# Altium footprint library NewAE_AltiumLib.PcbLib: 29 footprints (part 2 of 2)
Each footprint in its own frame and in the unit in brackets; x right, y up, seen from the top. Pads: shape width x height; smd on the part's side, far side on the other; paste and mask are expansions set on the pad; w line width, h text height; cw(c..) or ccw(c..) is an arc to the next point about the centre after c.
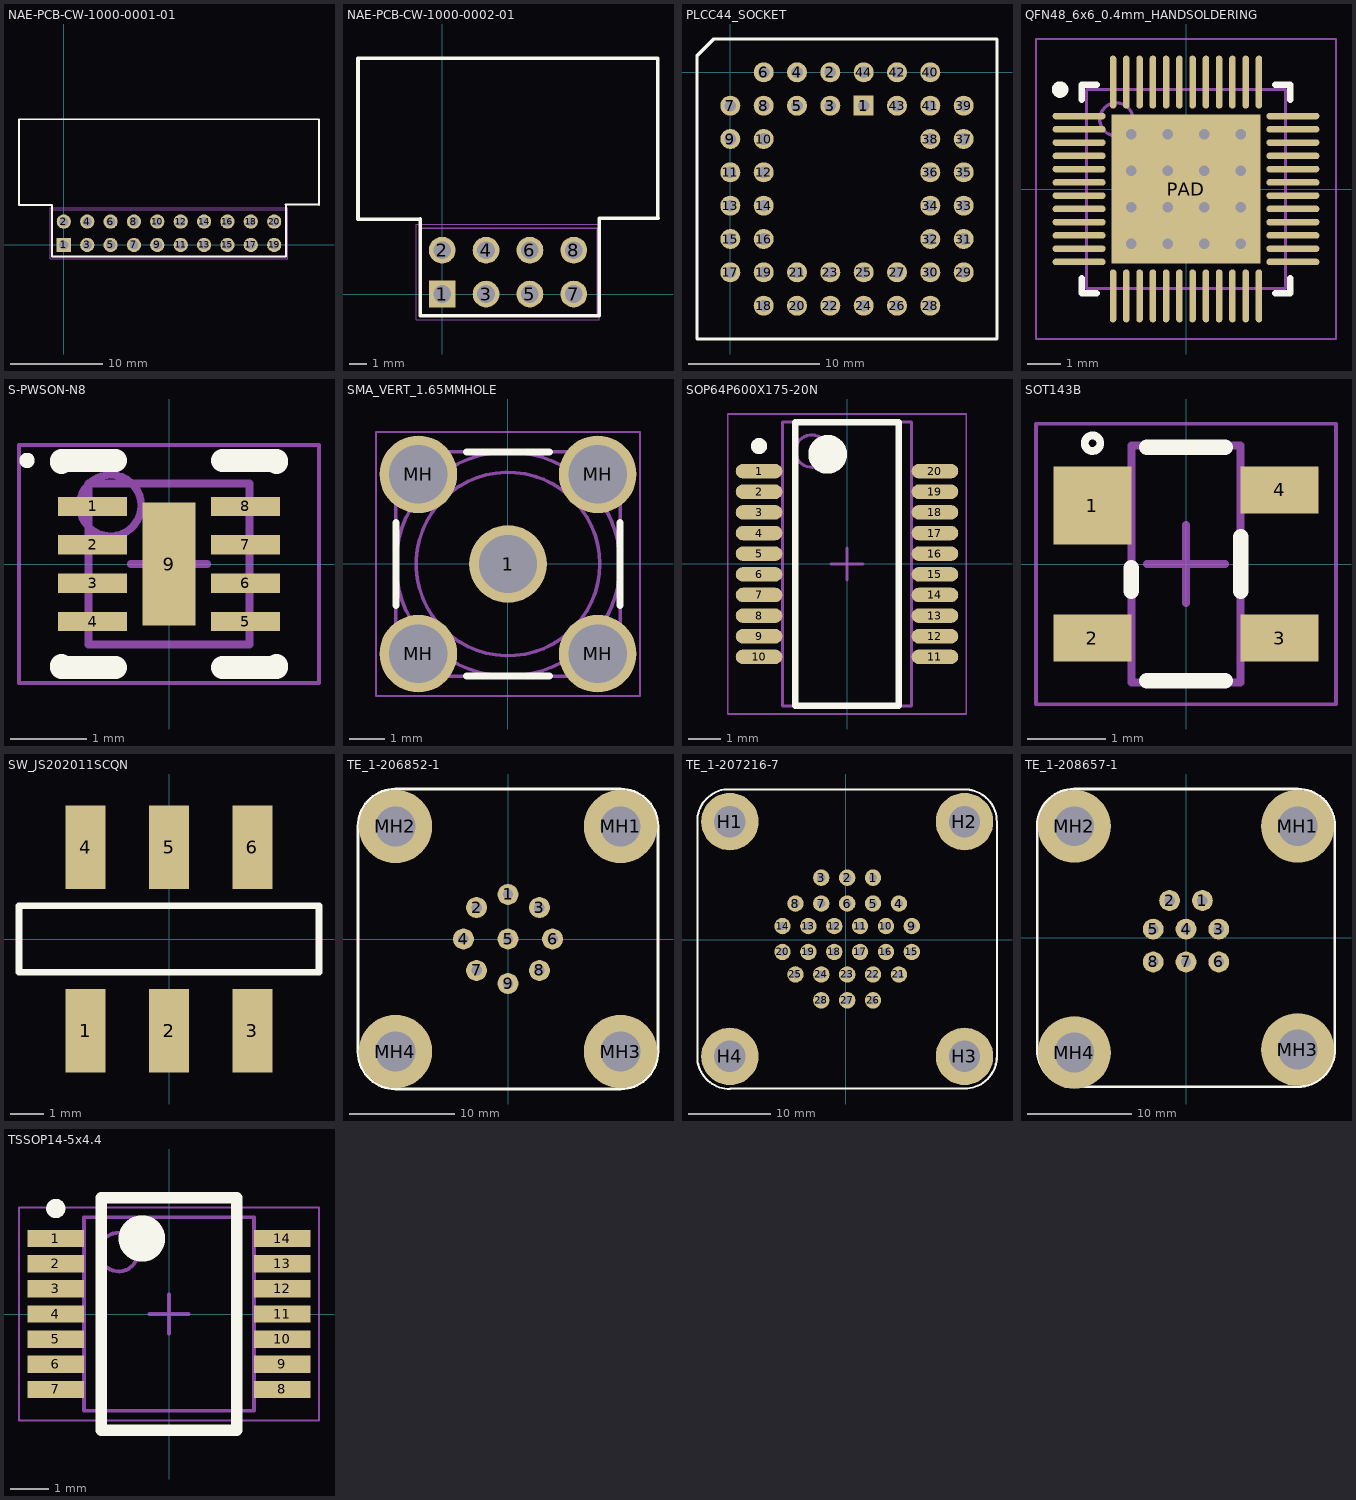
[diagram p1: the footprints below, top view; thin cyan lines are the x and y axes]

## NAE-PCB-CW-1000-0001-01 [mm] "High Temp Terminal Body, 2x10 Pins, R/A, 2.54mm Pitch, Male"
height 9.2
pads (20):
  rect 1.55x1.55 hole 1.02: 1(0,0)
  round 1.55 hole 1.02: 2(0,2.54) 3(2.54,0) 4(2.54,2.54) 5(5.08,0) 6(5.08,2.54) 7(7.62,0) 8(7.62,2.54) 9(10.16,0) 10(10.16,2.54) 11(12.7,0) 12(12.7,2.54) 13(15.24,0) 14(15.24,2.54) 15(17.78,0) 16(17.78,2.54) 17(20.32,0) 18(20.32,2.54) 19(22.86,0) 20(22.86,2.54)
Top Overlay:
  lines w0.2: -1.27,3.81 -1.27,-1.27 24.13,-1.27 24.13,3.81
  lines w0.203: -1.27,3.81 -1.27,4.37 -1.3,4.34 -4.875,4.34 -4.875,13.66 -4.875,13.66 27.735,13.66 ; 24.13,3.81 24.13,4.37 24.1,4.4 27.675,4.4 27.735,4.34 27.735,13.66 ; 27.735,13.66 27.735,13.66
Top 3D:
  lines w0.1: -1.27,-1.27 24.13,-1.27 24.13,3.81 -1.27,3.81 -1.27,-1.27
Top Courtyard:
  lines w0.05: -1.495,-1.495 24.355,-1.495 24.355,4.035 -1.495,4.035 -1.495,-1.495
3D body "75867_y04_asm.stp": height 9.27, standoff -3.07, extent -4.875,-0.31 27.735,13.66

## NAE-PCB-CW-1000-0002-01 [mm] "High Temp Terminal Body, 2x4 Pins, R/A, 2.54mm Pitch, Male"
height 9.2
pads (8):
  rect 1.55x1.55 hole 1.02: 1(0,0)
  round 1.55 hole 1.02: 2(0,2.54) 3(2.54,0) 4(2.54,2.54) 5(5.08,0) 7(7.62,0) 8(7.62,2.54)
  round 1.55 hole 1.02 mask+0.102: 6(5.08,2.54)
Top Overlay:
  lines w0.2: -1.27,3.81 -1.27,-1.27 9.1,-1.27
  lines w0.203: -1.27,3.81 -1.27,4.37 -1.3,4.34 -4.875,4.34 -4.875,13.66 -4.875,13.66 12.495,13.66 12.495,4.405 ; 9.1,-1.27 9.1,4.4 ; 9.13,4.37 9.1,4.4 ; 12.5,4.4 9.1,4.4
Top 3D:
  lines w0.1: -1.27,-1.27 9,-1.27 9,3.81 -1.27,3.81 -1.27,-1.27
Top Courtyard:
  lines w0.05: -1.495,-1.495 9.1,-1.495 9.1,-0.113 9.1,2.653 9.1,4.035 -1.495,4.035 -1.495,-1.495
3D body "75867132lf.stp": height 9.27, standoff -3.07, extent -4.875,-0.31 12.495,13.66

## PLCC44_SOCKET [mil]
pads (44):
  rect 60x60 hole 35: 1(400,-100)
  round 60 hole 35: 2(300,0) 3(300,-100) 4(200,0) 5(200,-100) 6(100,0) 7(0,-100) 8(100,-100) 9(0,-200) 10(100,-200) 11(0,-300) 12(100,-300) 13(0,-400) 14(100,-400) 15(0,-500) 16(100,-500) 17(0,-600) 18(100,-700) 19(100,-600) 20(200,-700) 21(200,-600) 22(300,-700) 23(300,-600) 24(400,-700) 25(400,-600) 26(500,-700) 27(500,-600) 28(600,-700) 29(700,-600) 30(600,-600) 31(700,-500) 32(600,-500) 33(700,-400) 34(600,-400) 35(700,-300) 36(600,-300) 37(700,-200) 38(600,-200) 39(700,-100) 40(600,0) 41(600,-100) 42(500,0) 43(500,-100) 44(400,0)
Top Overlay:
  lines w10: -100,-800 -100,50 -50,100 800,100 800,-800 -100,-800
3D body "10376.stp": height 301.57, standoff -129.92, extent -91.92,-791.92 791.94,91.94

## QFN48_6x6_0.4mm_HANDSOLDERING [mm] "QFN48, 6x6 body, hand soldering (long leads)"
height 0.8
pads (49):
  oval 1.6x0.2 smd: 1(-3.225,2.2) 2(-3.225,1.8) 3(-3.225,1.4) 4(-3.225,1) 5(-3.225,0.6) 6(-3.225,0.2) 7(-3.225,-0.2) 8(-3.225,-0.6) 9(-3.225,-1) 10(-3.225,-1.4) 11(-3.225,-1.8) 12(-3.225,-2.2) 25(3.225,-2.2) 26(3.225,-1.8) 27(3.225,-1.4) 28(3.225,-1) 29(3.225,-0.6) 30(3.225,-0.2) 31(3.225,0.2) 32(3.225,0.6) 33(3.225,1) 34(3.225,1.4) 35(3.225,1.8) 36(3.225,2.2)
  oval 0.2x1.6 smd: 13(-2.2,-3.225) 14(-1.8,-3.225) 15(-1.4,-3.225) 16(-1,-3.225) 17(-0.6,-3.225) 18(-0.2,-3.225) 19(0.2,-3.225) 20(0.6,-3.225) 21(1,-3.225) 22(1.4,-3.225) 23(1.8,-3.225) 24(2.2,-3.225) 37(2.2,3.225) 38(1.8,3.225) 39(1.4,3.225) 40(1,3.225) 41(0.6,3.225) 42(0.2,3.225) 43(-0.2,3.225) 44(-0.6,3.225) 45(-1,3.225) 46(-1.4,3.225) 47(-1.8,3.225) 48(-2.2,3.225)
  rect 4.5x4.5 smd: PAD(0,0)
via -1.65,1.65 diameter 0.6 hole 0.32
via -0.55,1.65 diameter 0.6 hole 0.32
via 0.55,1.65 diameter 0.6 hole 0.32
via 1.65,1.65 diameter 0.6 hole 0.32
via -1.65,0.55 diameter 0.6 hole 0.32
via -0.55,0.55 diameter 0.6 hole 0.32
via 0.55,0.55 diameter 0.6 hole 0.32
via 1.65,0.55 diameter 0.6 hole 0.32
via -1.65,-0.55 diameter 0.6 hole 0.32
via -0.55,-0.55 diameter 0.6 hole 0.32
via 0.55,-0.55 diameter 0.6 hole 0.32
via 1.65,-0.55 diameter 0.6 hole 0.32
via -1.65,-1.65 diameter 0.6 hole 0.32
via -0.55,-1.65 diameter 0.6 hole 0.32
via 0.55,-1.65 diameter 0.6 hole 0.32
via 1.65,-1.65 diameter 0.6 hole 0.32
Top Overlay:
  circle w0.25: c-3.8,3 r0.125
  lines w0.2: -3.15,-2.7 -3.15,-3.15 -2.7,-3.15 ; -3.15,2.7 -3.15,3.15 -2.7,3.15 ; 2.7,-3.15 3.15,-3.15 3.15,-2.7 ; 2.7,3.15 3.15,3.15 3.15,2.7
Top 3D:
  circle w0.1: c-2.1,2.1 r0.5
  lines w0.1: -3,-3 -3,3 3,3 3,-3 -3,-3
Top Courtyard:
  lines w0.05: -4.525,-4.525 -4.525,4.525 4.525,4.525 4.525,-4.525 -4.525,-4.525
  lines w0.1: -0.5,0 0.5,0 ; 0,-0.5 0,0.5
3D body "QFN48_6x6_0.4mm_HANDSOLDERING.step": height 0.8, standoff 0, extent -3.01,-3.01 3.01,3.01

## S-PWSON-N8 [mm] "SON, 8-Leads, Body 2.00x2.00mm, Pitch 0.50mm, Thermal Pad 1.60x0.69mm, IPC Low Density"
height 0.8
pads (9):
  rect 0.9x0.25 smd: 1(-0.995,0.75) 2(-0.995,0.25) 3(-0.995,-0.25) 4(-0.995,-0.75) 5(0.995,-0.75) 6(0.995,-0.25) 7(0.995,0.25) 8(0.995,0.75)
  rect 0.69x1.6 smd: 9(0,0)
Top Overlay:
  circle w0.1: c-1.85,1.35 r0.05
  lines w0.3: -1.4,-1.325 -1.4,-1.35 -0.695,-1.35 ; -1.4,1.325 -1.4,1.35 -0.695,1.35 ; 0.695,-1.35 1.4,-1.35 1.4,-1.325 ; 0.695,1.35 1.4,1.35 1.4,1.325
Top 3D:
  circle w0.1: c-0.762,0.762 r0.4
  lines w0.1: -1.05,-1.05 -1.05,1.05 1.05,1.05 1.05,-1.05 -1.05,-1.05
Top Courtyard:
  lines w0.05: -1.955,-1.55 -1.955,1.55 1.955,1.55 1.955,-1.55 -1.955,-1.55
  lines w0.1: -0.5,0 0.5,0 ; 0,-0.5 0,0.5
3D body "S-PWSON-N8.step": height 0.8, standoff 0, extent -1.1,-1.05 1.1,1.05

## SMA_VERT_1.65MMHOLE [mm] "SMA Straight Jack, 6.35x6.35x9.5mm, Rosenberger Recommended"
height 9.5
pads (5):
  round 2.2 hole 1.65: 1(0,0) MH(-2.54,-2.54) MH(-2.54,2.54) MH(2.54,-2.54) MH(2.54,2.54)
Top Overlay:
  lines w0.2: -3.175,-1.181 -3.175,1.181 ; -1.181,-3.175 1.181,-3.175 ; -1.181,3.175 1.181,3.175 ; 3.175,-1.181 3.175,1.181
Top 3D:
  circle w0.1: c0,0 r0.635
  circle w0.1: c0,0 r2.6
  circle w0.1: c0,0 r3.175
  lines w0.1: -3.19,-2.808 ccw(c0,0) -2.808,-3.191 ; -3.19,2.808 cw(c0,0) -2.808,3.19 ; -3.175,-2.794 -3.175,2.794 ; -3.04,-2.97 -3.04,-2.04 -2.04,-2.04 -2.04,-3.04 -2.97,-3.04 ; -3.04,2.97 -3.04,2.04 -2.04,2.04 -2.04,3.04 -2.97,3.04 ; -2.794,-3.175 2.794,-3.175 ; -2.794,3.175 2.794,3.175 ; -0.1,-0.627 -0.1,0.627 ; 0.1,-0.627 0.1,0.627 ; 2.808,-3.191 ccw(c0,0) 3.191,-2.808 ; 2.808,3.19 cw(c0,0) 3.191,2.808 ; 2.97,3.04 2.04,3.04 2.04,2.04 3.04,2.04 3.04,2.97 ; 2.97,-3.04 2.04,-3.04 2.04,-2.04 3.04,-2.04 3.04,-2.97 ; 3.175,-2.794 3.175,2.794
Top Courtyard:
  lines w0.05: -3.74,-3.74 3.74,-3.74 3.74,3.74 -3.74,3.74 -3.74,-3.74
  lines w0.1: -0.635,0 0.508,0 ; 0,-0.508 0,0.635
3D body "32k101-400l5.stp": height 9.5, standoff -4, extent -3.175,-3.175 3.175,3.175

## SOP64P600X175-20N [mm] "SOP, 20-Leads, Body 8.66x3.91mm, Pitch 0.64mm, IPC Medium Density"
height 1.75
pads (20):
  oval 1.45x0.45 smd: 1(-2.725,2.88) 2(-2.725,2.24) 3(-2.725,1.6) 4(-2.725,0.96) 5(-2.725,0.32) 6(-2.725,-0.32) 7(-2.725,-0.96) 8(-2.725,-1.6) 9(-2.725,-2.24) 10(-2.725,-2.88) 11(2.725,-2.88) 12(2.725,-2.24) 13(2.725,-1.6) 14(2.725,-0.96) 15(2.725,-0.32) 16(2.725,0.32) 17(2.725,0.96) 18(2.725,1.6) 19(2.725,2.24) 20(2.725,2.88)
Top Overlay:
  circle w0.6: c-0.6,3.4 r0.3
  circle w0.25: c-2.725,3.655 r0.125
  lines w0.2: -1.6,-4.4 1.6,-4.4 1.6,4.4 -1.6,4.4 -1.6,-4.4
Top 3D:
  circle w0.1: c-1.1,3.5 r0.5
  lines w0.1: -2,-4.4 2,-4.4 2,4.4 -2,4.4 -2,-4.4
Top Courtyard:
  lines w0.05: -3.7,-4.65 3.7,-4.65 3.7,4.65 -3.7,4.65 -3.7,-4.65
  lines w0.1: -0.5,0 0.5,0 ; 0,-0.5 0,0.5
3D body "SOP64P600X175-20N.step": height 1.75, standoff 0, extent -2.997,-4.4 2.997,4.4

## SOT143B [mm] "SOT143, 4-Leads, Body 2.92x2.37mm, Pitch 1.90mm, IPC Medium Density"
height 1.2
pads (4):
  rect 1x1 smd: 1(-1.2,0.75)
  rect 1x0.6 smd: 2(-1.2,-0.95) 3(1.2,-0.95) 4(1.2,0.95)
Top Overlay:
  circle w0.1: c-1.2,1.55 r0.1
  lines w0.2: -0.7,-0.35 -0.7,-0.05 ; -0.5,-1.5 0.5,-1.5 ; -0.5,1.5 0.5,1.5 ; 0.7,-0.35 0.7,0.35
Top 3D:
  lines w0.1: -0.7,-1.52 -0.7,1.52 0.7,1.52 0.7,-1.52 -0.7,-1.52
Top Courtyard:
  lines w0.05: -1.925,-1.8 -1.925,1.8 1.925,1.8 1.925,-1.8 -1.925,-1.8
  lines w0.1: -0.5,0 0.5,0 ; 0,-0.5 0,0.5
3D body "SOT143B.step": height 1.2, standoff 0.01, extent -1.179,-1.52 1.179,1.52

## SW_JS202011SCQN [mm]
pads (6):
  rect 1.2x2.5 smd paste-25.4 mask-25.4: 1(-2.5,-2.75) 2(0,-2.75) 3(2.5,-2.75) 4(-2.5,2.75) 5(0,2.75) 6(2.5,2.75)
Top Overlay:
  lines w0.2: -4.5,-1 4.5,-1 4.5,1 -4.5,1 -4.5,-1
Top Paste:
  region: 1.9,1.5 3.1,1.5 3.1,4 1.9,4
  region: -0.6,1.5 0.6,1.5 0.6,4 -0.6,4
  region: -3.1,1.5 -1.9,1.5 -1.9,4 -3.1,4
  region: 1.9,-4 3.1,-4 3.1,-1.5 1.9,-1.5
  region: -0.6,-4 0.6,-4 0.6,-1.5 -0.6,-1.5
  region: -3.1,-4 -1.9,-4 -1.9,-1.5 -3.1,-1.5
Top Solder:
  region: 1.8,1.4 3.2,1.4 3.2,4.1 1.8,4.1
  region: -0.7,1.4 0.7,1.4 0.7,4.1 -0.7,4.1
  region: -3.2,1.4 -1.8,1.4 -1.8,4.1 -3.2,4.1
  region: 1.8,-4.1 3.2,-4.1 3.2,-1.4 1.8,-1.4
  region: -0.7,-4.1 0.7,-4.1 0.7,-1.4 -0.7,-1.4
  region: -3.2,-4.1 -1.8,-4.1 -1.8,-1.4 -3.2,-1.4
3D body "js202011scqn.stp": height 5.5, standoff 0, extent -4.5,-3.75 4.5,3.75

## TE_1-206852-1 [mm] "TE 1-206852-1 (9-Pin Male Circular)"
pads (13):
  round 2 hole 1: 1(0,4.242) 2(-2.997,2.997) 3(2.997,2.997) 4(-4.242,0) 5(0,0) 6(4.242,0) 7(-3,-3) 8(3,-3) 9(0,-4.242)
  round 7 hole 3.81: MH1(10.719,10.719) MH2(-10.719,10.719) MH3(10.719,-10.719) MH4(-10.719,-10.719)
Top Overlay:
  lines w0.254: -14.287,-10.731 ccw(c-10.719,-10.719) -10.731,-14.287 10.731,-14.287 ccw(c10.719,-10.719) 14.287,-10.731 14.287,10.731 ccw(c10.719,10.719) 10.731,14.287 -10.731,14.287 ccw(c-10.719,10.719) -14.287,10.731 -14.287,-10.731
3D body "c-1-206852-1-ak-3d.stp": height 19.91, standoff -8.94, extent -14.287,-14.287 14.287,14.287

## TE_1-207216-7 [mm] "TE Round 1-207216-7"
pads (32):
  round 2 hole 1: 1(3.325,7.568) 2(0.175,7.568) 3(-2.975,7.568) 4(6.474,4.418) 5(3.325,4.418) 6(0.175,4.418) 7(-2.975,4.418) 8(-6.124,4.418) 9(8.049,1.675) 10(4.899,1.675) 11(1.75,1.675) 12(-1.4,1.675) 13(-4.549,1.675) 14(-7.699,1.675) 15(8.049,-1.475) 16(4.899,-1.475) 17(1.75,-1.475) 18(-1.4,-1.475) 19(-4.549,-1.475) 20(-7.699,-1.475) 21(6.474,-4.218) 22(3.325,-4.218) 23(0.175,-4.218) 24(-2.975,-4.218) 25(-6.124,-4.218) 26(3.325,-7.368) 27(0.175,-7.368) 28(-2.975,-7.368)
  round 7 hole 3.81: H1(-14.112,14.387) H2(14.462,14.387) H3(14.462,-14.188) H4(-14.112,-14.188)
Top Overlay:
  lines w0.254: -18.074,14.754 cw(c-14.112,14.387) -14.827,18.301 ; -18.03,14.75 -18.03,-14.878 ccw(c-14.112,-14.188) -14.087,-18.166 ; -14.803,18.305 14.825,18.305 ; -14.087,-18.125 14.806,-18.125 ; 14.733,18.313 cw(c14.462,14.387) 18.397,14.387 ; 14.805,-18.11 ccw(c14.462,-14.188) 18.4,-14.162 18.4,14.362
3D body "c-0207216-17-ad1-3d.stp": height 19.91, standoff -9.37, extent -18.05,-18.125 18.4,18.324

## TE_1-208657-1 [mm]
pads (12):
  round 2 hole 1: 1(1.575,3.581) 2(-1.575,3.581) 3(3.15,0.838) 4(0,0.838) 5(-3.15,0.838) 6(3.15,-2.311) 7(0,-2.311) 8(-3.15,-2.311)
  round 7 hole 3.81: MH1(10.719,10.719) MH2(-10.719,10.719) MH3(10.719,-10.719) MH4(-10.719,-11.006)
Top Overlay:
  lines w0.254: -14.27,-11.08 -14.27,11.08 ; -14.269,-11.08 ccw(c-10.719,-10.719) -10.731,-14.287 10.731,-14.287 ccw(c10.719,-10.719) 14.287,-10.713 14.287,10.731 ; -14.269,11.08 cw(c-10.719,10.719) -10.731,14.287 10.731,14.287 cw(c10.719,10.719) 14.288,10.719
3D body "c-1-208657-1-af-3d.stp": height 20.55, standoff -8.94, extent -14.287,-14.287 14.287,14.287

## TSSOP14-5x4.4 [mm]
height 1.75
pads (14):
  rect 1.45x0.45 smd: 1(-2.925,1.95) 2(-2.925,1.3) 3(-2.925,0.65) 4(-2.925,0) 5(-2.925,-0.65) 6(-2.925,-1.3) 7(-2.925,-1.95) 8(2.925,-1.95) 9(2.925,-1.3) 10(2.925,-0.65) 11(2.925,0) 12(2.925,0.65) 13(2.925,1.3) 14(2.925,1.95)
Top Overlay:
  circle w0.25: c-2.925,2.725 r0.125
  circle w0.6: c-0.7,1.95 r0.3
  lines w0.3: -1.75,-3 -1.75,3 1.75,3 1.75,-3 -1.75,-3
Top 3D:
  circle w0.1: c-1.3,1.6 r0.5
  lines w0.1: -2.2,-2.5 -2.2,2.5 2.2,2.5 2.2,-2.5 -2.2,-2.5
Top Courtyard:
  lines w0.05: -3.875,-2.75 -3.875,2.75 3.875,2.75 3.875,-2.75 -3.875,-2.75
  lines w0.1: -0.5,0 0.5,0 ; 0,-0.5 0,0.5
3D body "TSSOP14-5x4.4.step": height 1.75, standoff 0, extent -3.2,-2.5 3.2,2.5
